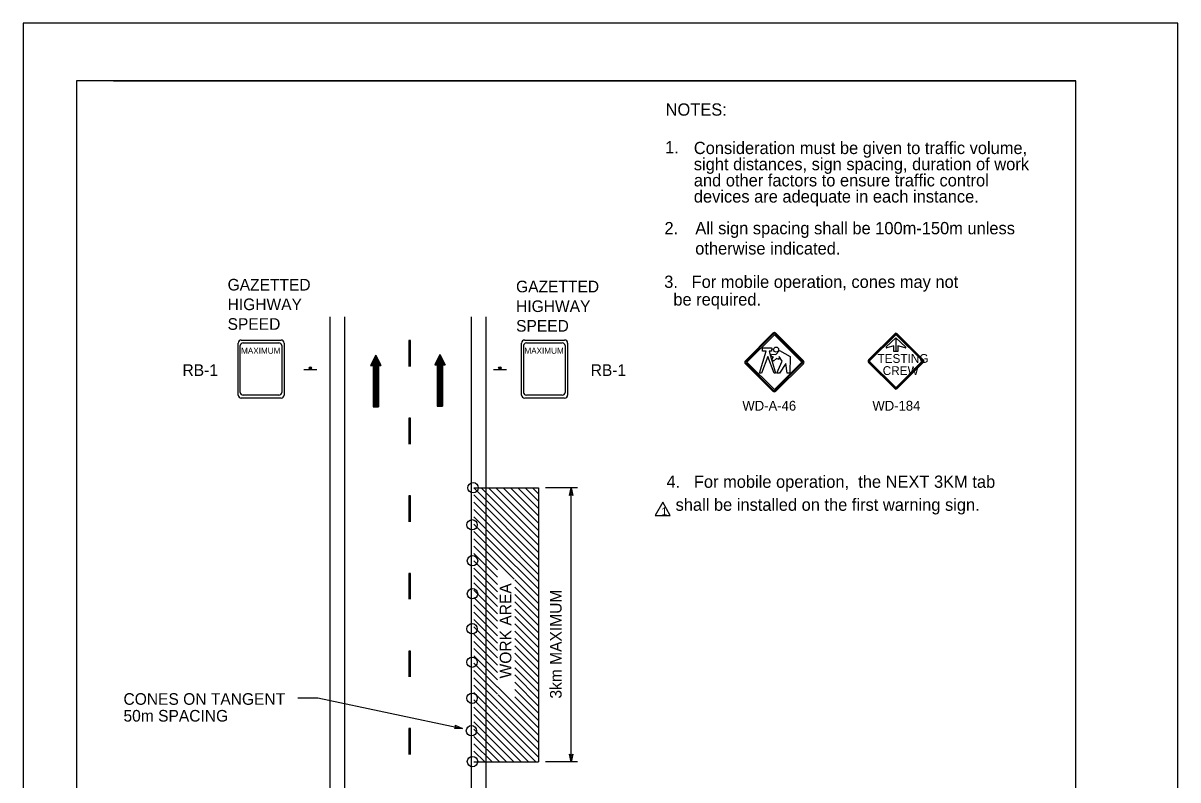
# Model space of a CAD drawing. Extents: x 1333 to 1549, y 120 to 399.
# Drawn here: x 1333.4 to 1549.4, y 257.2 to 398.8 of the extents above; entities that cross this region are included whole.
import ezdxf

# ---------------------------------------------------------------- set-up
doc = ezdxf.new("R2010")
doc.units = 0
for name, color, linetype in [('Level 1', 7, 'Continuous'), ('Level 10', 7, 'Continuous'), ('Level 2', 7, 'Continuous'), ('Level 22', 7, 'Continuous'), ('Level 3', 7, 'Continuous'), ('Level 44', 7, 'Continuous'), ('Level 60', 7, 'Continuous'), ('Level 61', 7, 'Continuous'), ('Level 62', 7, 'Continuous')]:
    doc.layers.add(name, color=color, linetype=linetype)

msp = doc.modelspace()

# ---------------------------------------------------------------- linework, layer by layer
at = {"layer": 'Level 1'}
for p, q in [((1468.47, 335.62), (1473.6, 340.75)), ((1468.62, 335.48), (1473.74, 340.61)), ((1468.76, 335.34), (1473.88, 340.46)), ((1473.85, 341.01), (1473.85, 341.01)), ((1473.89, 341.04), (1473.89, 341.04)), ((1473.89, 340.46), (1479.02, 335.34)), ((1474.03, 340.61), (1479.16, 335.48)), ((1474.18, 340.75), (1479.31, 335.62)), ((1491.5, 335.76), (1496.4, 340.66)), ((1496.49, 340.57), (1491.59, 335.67)), ((1491.59, 335.67), (1496.49, 340.57)), ((1491.68, 335.58), (1496.58, 340.48)), ((1496.62, 339.87), (1496.62, 337.35)), ((1496.67, 340.48), (1501.56, 335.58)), ((1496.85, 340.66), (1501.74, 335.76)), ((1473.6, 329.92), (1468.47, 335.05)), ((1473.74, 330.06), (1468.62, 335.19)), ((1473.88, 330.2), (1468.76, 335.33)), ((1473.85, 335.24), (1473.85, 335.24)), ((1479.02, 335.33), (1473.89, 330.2)), ((1479.16, 335.19), (1474.03, 330.06)), ((1479.31, 335.05), (1474.18, 329.92)), ((1496.4, 330.42), (1491.5, 335.31)), ((1496.58, 330.59), (1491.68, 335.49)), ((1496.64, 330.62), (1501.54, 335.52)), ((1496.64, 330.62), (1501.54, 335.52)), ((1496.64, 330.62), (1501.54, 335.52)), ((1501.54, 335.52), (1496.64, 330.62)), ((1501.56, 335.49), (1496.67, 330.59)), ((1501.74, 335.31), (1496.85, 330.42)), ((1501.97, 335.54), (1501.97, 335.54))]:
    msp.add_line(p, q, dxfattribs=at)
for points in [[(1472.32, 337.42), (1471.69, 337.42), (1471.69, 338.02), (1473.34, 338.02), (1473.34, 337.93), (1473.41, 337.93), (1473.41, 337.69), (1473.34, 337.69), (1473.34, 337.42), (1472.88, 337.42), (1474.09, 333.29), (1473.83, 333.29), (1472.64, 336.41), (1471.45, 333.29), (1471.13, 333.29)], [(1472.32, 337.42), (1471.69, 337.42), (1471.69, 338.02), (1473.34, 338.02), (1473.34, 337.93), (1473.41, 337.93), (1473.41, 337.69), (1473.34, 337.69), (1473.34, 337.42), (1472.88, 337.42), (1474.09, 333.29), (1473.83, 333.29), (1472.64, 336.41), (1471.45, 333.29), (1471.13, 333.29)], [(1473.32, 336.85), (1474.18, 336.77), (1474.87, 337.55), (1476.82, 336.42), (1476.76, 333.29), (1476.29, 333.29), (1476.01, 335.08), (1474.87, 333.29), (1474.35, 333.29), (1475.33, 335.51), (1474.81, 336.41), (1474.71, 335.85), (1474.26, 336.03), (1473.71, 335.51), (1473.37, 335.82), (1473.74, 336.25), (1473.24, 336.48)], [(1473.32, 336.85), (1474.18, 336.77), (1474.87, 337.55), (1476.82, 336.42), (1476.76, 333.29), (1476.29, 333.29), (1476.01, 335.08), (1474.87, 333.29), (1474.35, 333.29), (1475.33, 335.51), (1474.81, 336.41), (1474.71, 335.85), (1474.26, 336.03), (1473.71, 335.51), (1473.37, 335.82), (1473.74, 336.25), (1473.24, 336.48)], [(1452.99, 309.13), (1451.57, 306.66), (1454.4, 306.66)]]:
    msp.add_lwpolyline(points, close=True, dxfattribs=at)
for centre, radius, start, end in [((1473.89, 340.46), 0.409, 45.0349, 135), ((1473.89, 340.46), 0.208, 45.0349, 135), ((1473.89, 340.46), 0.00624, 45.0349, 135), ((1496.62, 340.43), 0.32, 44.9995, 135.0002), ((1496.62, 340.43), 0.194, 44.9995, 135.0002), ((1496.62, 340.43), 0.194, 44.9995, 135.0002), ((1496.62, 340.43), 0.068, 44.9995, 135.0002), ((1496.62, 340.43), 0.026, 45, 135), ((1496.62, 340.43), 0.026, 45, 135), ((1496.62, 340.43), 0.026, 45, 135), ((1468.76, 335.33), 0.409, 135, 224.9651), ((1468.76, 335.33), 0.208, 135, 224.9651), ((1468.76, 335.33), 0.00624, 135, 224.9651), ((1479.02, 335.33), 0.00624, 315, 45.0346), ((1479.02, 335.33), 0.208, 315, 45.0346), ((1479.02, 335.33), 0.409, 315, 45.0346), ((1491.73, 335.54), 0.32, 135.0005, 225), ((1491.73, 335.54), 0.194, 135.0005, 225), ((1491.73, 335.54), 0.194, 135.0005, 225), ((1491.73, 335.54), 0.194, 135.0005, 225), ((1491.73, 335.54), 0.068, 135.0005, 225), ((1501.52, 335.54), 0.026, 315, 45), ((1501.52, 335.54), 0.026, 315, 45), ((1501.52, 335.54), 0.026, 315, 45), ((1501.52, 335.54), 0.068, 315.0005, 44.9999), ((1501.52, 335.54), 0.194, 315.0005, 44.9999), ((1501.52, 335.54), 0.194, 315.0005, 44.9999), ((1501.52, 335.54), 0.32, 315.0005, 44.9999), ((1496.62, 330.64), 0.068, 224.9995, 315), ((1496.62, 330.64), 0.026, 225, 315), ((1496.62, 330.64), 0.026, 225, 315), ((1496.62, 330.64), 0.026, 225, 315), ((1473.89, 330.21), 0.409, 224.965, 315), ((1473.89, 330.21), 0.208, 224.965, 315), ((1473.89, 330.21), 0.00624, 224.965, 315), ((1496.62, 330.64), 0.32, 224.9995, 315)]:
    msp.add_arc(centre, radius, start, end, dxfattribs=at)
at = {"layer": 'Level 10'}
for p, q in [((1390.76, 343.79), (1390.76, 162.28)), ((1393.49, 343.79), (1393.49, 162.28)), ((1417.2, 343.79), (1417.2, 162.28)), ((1419.94, 343.79), (1419.94, 162.28)), ((1399.33, 336.66), (1398.36, 334.72)), ((1398.48, 334.97), (1398.48, 334.72)), ((1398.6, 335.21), (1398.6, 334.72)), ((1398.73, 335.45), (1398.73, 334.72)), ((1398.85, 335.69), (1398.85, 326.98)), ((1398.97, 335.93), (1398.97, 326.98)), ((1399.09, 336.18), (1399.09, 326.98)), ((1399.21, 336.42), (1399.21, 326.98)), ((1399.33, 336.66), (1399.33, 326.98)), ((1399.33, 336.66), (1400.3, 334.72)), ((1399.45, 336.42), (1399.45, 326.98)), ((1399.57, 336.18), (1399.57, 326.98)), ((1399.69, 335.93), (1399.69, 326.98)), ((1399.81, 335.69), (1399.81, 326.98)), ((1399.93, 335.45), (1399.93, 334.72)), ((1400.06, 335.21), (1400.06, 334.72)), ((1400.18, 334.97), (1400.18, 334.72)), ((1411.32, 336.78), (1410.35, 334.85)), ((1410.35, 334.85), (1410.83, 334.85)), ((1410.47, 335.09), (1410.47, 334.85)), ((1410.59, 335.33), (1410.59, 334.85)), ((1410.71, 335.57), (1410.71, 334.85)), ((1410.83, 335.82), (1410.83, 327.11)), ((1410.83, 334.85), (1410.83, 327.11)), ((1410.95, 336.06), (1410.95, 327.11)), ((1411.07, 336.3), (1411.07, 327.11)), ((1411.19, 336.54), (1411.19, 327.11)), ((1411.32, 336.78), (1411.32, 327.11)), ((1411.32, 336.78), (1412.28, 334.85)), ((1411.44, 336.54), (1411.44, 327.11)), ((1411.56, 336.3), (1411.56, 327.11)), ((1411.68, 336.06), (1411.68, 327.11)), ((1411.8, 335.82), (1411.8, 327.11)), ((1411.8, 334.85), (1411.8, 327.11)), ((1411.8, 334.85), (1412.28, 334.85)), ((1411.92, 335.57), (1411.92, 334.85)), ((1412.04, 335.33), (1412.04, 334.85)), ((1412.16, 335.09), (1412.16, 334.85)), ((1398.36, 334.72), (1398.85, 334.72)), ((1398.85, 334.72), (1398.85, 326.98)), ((1399.81, 334.72), (1399.81, 326.98)), ((1399.81, 334.72), (1400.3, 334.72)), ((1398.85, 326.98), (1399.81, 326.98)), ((1410.83, 327.11), (1411.8, 327.11)), ((1417.68, 311.86), (1429.78, 311.86)), ((1417.68, 311.86), (1429.78, 299.77)), ((1417.68, 311.86), (1429.78, 311.86)), ((1419.05, 311.86), (1429.78, 301.14)), ((1420.42, 311.86), (1429.78, 302.51)), ((1421.79, 311.86), (1429.78, 303.88)), ((1423.16, 311.86), (1429.78, 305.24)), ((1424.53, 311.86), (1429.78, 306.61)), ((1425.89, 311.86), (1429.78, 307.98)), ((1427.26, 311.86), (1429.78, 309.35)), ((1428.63, 311.86), (1429.78, 310.72)), ((1429.78, 311.86), (1429.78, 260.58)), ((1437.06, 311.86), (1431.05, 311.86)), ((1435.87, 260.58), (1435.87, 311.86)), ((1417.68, 310.5), (1429.78, 298.4)), ((1417.68, 309.13), (1424.43, 302.38)), ((1417.68, 307.76), (1423.07, 302.38)), ((1417.68, 306.39), (1422.12, 301.95)), ((1417.68, 305.02), (1422.12, 300.58)), ((1417.68, 303.65), (1425.36, 295.98)), ((1417.68, 302.29), (1425.19, 294.78)), ((1417.68, 300.92), (1422.12, 296.48)), ((1421.44, 301.27), (1429.78, 292.93)), ((1422.12, 301.95), (1429.78, 294.3)), ((1423.07, 302.38), (1429.78, 295.66)), ((1424.43, 302.38), (1429.78, 297.03)), ((1417.68, 299.55), (1422.12, 295.11)), ((1417.68, 298.18), (1422.12, 293.74)), ((1417.68, 296.81), (1422.12, 292.38)), ((1425.34, 295.99), (1429.78, 291.56)), ((1417.68, 295.44), (1422.12, 291.01)), ((1417.68, 294.07), (1422.12, 289.64)), ((1425.34, 294.62), (1429.78, 290.19)), ((1417.68, 292.71), (1422.12, 288.27)), ((1425.34, 293.26), (1429.78, 288.82)), ((1425.34, 291.89), (1429.78, 287.45)), ((1417.68, 291.34), (1422.12, 286.9)), ((1417.68, 289.97), (1422.12, 285.53)), ((1425.34, 290.52), (1429.78, 286.09)), ((1417.68, 288.6), (1417.69, 288.59)), ((1417.68, 288.6), (1422.12, 284.16)), ((1425.34, 289.15), (1429.78, 284.72)), ((1425.34, 287.78), (1429.78, 283.35)), ((1417.68, 287.23), (1422.12, 282.8)), ((1417.68, 285.87), (1422.12, 281.43)), ((1425.34, 286.41), (1429.78, 281.98)), ((1417.68, 284.5), (1422.12, 280.06)), ((1417.68, 283.13), (1422.12, 278.69)), ((1425.34, 285.05), (1429.78, 280.61)), ((1425.34, 283.68), (1429.78, 279.24)), ((1417.68, 281.76), (1422.12, 277.32)), ((1425.34, 282.31), (1429.78, 277.88)), ((1425.34, 280.94), (1429.78, 276.51)), ((1417.68, 280.39), (1422.12, 275.95)), ((1417.68, 279.02), (1422.12, 274.59)), ((1425.34, 279.57), (1429.78, 275.14)), ((1417.68, 277.66), (1422.12, 273.22)), ((1425.34, 278.2), (1429.78, 273.77)), ((1425.34, 276.84), (1429.78, 272.4)), ((1417.68, 276.29), (1422.12, 271.85)), ((1417.68, 274.92), (1422.12, 270.48)), ((1422.07, 274.63), (1429.78, 266.93)), ((1425.34, 275.47), (1429.78, 271.03)), ((1384.77, 272.57), (1388.49, 272.57)), ((1388.49, 272.57), (1415.56, 266.86)), ((1417.68, 273.55), (1422.12, 269.11)), ((1417.68, 272.18), (1422.12, 267.74)), ((1422.2, 273.14), (1429.78, 265.56)), ((1425.34, 274.1), (1429.78, 269.67)), ((1425.34, 272.73), (1429.78, 268.3)), ((1417.68, 270.81), (1427.91, 260.58)), ((1422.05, 271.92), (1429.78, 264.19)), ((1422.19, 270.41), (1429.78, 262.82)), ((1417.68, 269.44), (1426.55, 260.58)), ((1417.68, 268.08), (1425.18, 260.58)), ((1422.13, 269.1), (1429.78, 261.45)), ((1417.68, 266.71), (1423.81, 260.58)), ((1422.11, 267.75), (1429.28, 260.58)), ((1417.68, 265.34), (1422.44, 260.58)), ((1417.68, 263.97), (1421.07, 260.58)), ((1417.68, 262.6), (1419.7, 260.58)), ((1417.68, 260.58), (1429.78, 260.58)), ((1437.06, 260.58), (1431.05, 260.58))]:
    msp.add_line(p, q, dxfattribs=at)
for points in [[(1435.87, 311.86), (1436.17, 310.41), (1435.87, 310.65), (1435.57, 310.41)], [(1415.56, 266.86), (1414.08, 266.86), (1414.37, 267.11), (1414.2, 267.45)], [(1435.87, 260.58), (1435.57, 262.03), (1435.87, 261.79), (1436.17, 262.03)]]:
    msp.add_lwpolyline(points, close=True, dxfattribs=at)
for centre in [(1417.52, 311.86), (1417.33, 304.93), (1417.42, 298.2), (1417.42, 292.04), (1417.33, 285.49), (1417.33, 279.23), (1417.33, 272.49), (1417.23, 266.42), (1417.42, 260.64)]:
    msp.add_circle(centre, 0.968, dxfattribs=at)
at = {"layer": 'Level 2'}
for p, q in [((1405.51, 339.37), (1405.51, 334.53)), ((1405.8, 339.37), (1405.51, 339.37)), ((1405.8, 334.53), (1405.8, 339.37)), ((1405.51, 324.85), (1405.51, 320.01)), ((1405.8, 324.85), (1405.51, 324.85)), ((1405.8, 320.01), (1405.8, 324.85)), ((1405.51, 310.34), (1405.51, 305.5)), ((1405.8, 310.34), (1405.51, 310.34)), ((1405.8, 305.5), (1405.8, 310.34)), ((1405.51, 295.82), (1405.51, 290.99)), ((1405.8, 295.82), (1405.51, 295.82)), ((1405.8, 290.99), (1405.8, 295.82)), ((1405.51, 281.31), (1405.51, 276.47)), ((1405.8, 281.31), (1405.51, 281.31)), ((1405.8, 276.47), (1405.8, 281.31)), ((1405.51, 266.8), (1405.51, 261.96)), ((1405.8, 266.8), (1405.51, 266.8)), ((1405.8, 261.96), (1405.8, 266.8))]:
    msp.add_line(p, q, dxfattribs=at)
for centre, radius, start, end in [((1496.62, 340.43), 0.32, 44.9995, 135.0002), ((1496.62, 340.43), 0.194, 44.9995, 135.0002), ((1491.73, 335.54), 0.32, 135.0005, 225), ((1501.52, 335.54), 0.194, 315.0005, 44.9999), ((1501.52, 335.54), 0.32, 315.0005, 44.9999), ((1496.62, 330.64), 0.194, 224.9995, 315)]:
    msp.add_arc(centre, radius, start, end, dxfattribs=at)
at = {"layer": 'Level 22'}
msp.add_line((1350.24, 387.94), (1530.24, 387.94), dxfattribs=at)
at = {"layer": 'Level 3'}
for centre, start, end in [((1496.62, 340.43), 45, 135), ((1496.62, 340.43), 45, 135), ((1501.52, 335.54), 315, 45), ((1501.52, 335.54), 315, 45), ((1496.62, 330.64), 225, 315), ((1496.62, 330.64), 225, 315)]:
    msp.add_arc(centre, 0.026, start, end, dxfattribs=at)
at = {"layer": 'Level 44'}
for p, q in [((1374.18, 339.48), (1381.63, 339.48)), ((1427.18, 339.48), (1434.63, 339.48)), ((1373.61, 329.2), (1373.61, 338.91)), ((1373.99, 329.69), (1373.99, 338.43)), ((1374.51, 338.95), (1381.21, 338.95)), ((1381.73, 338.43), (1381.73, 329.69)), ((1382.2, 338.91), (1382.2, 329.2)), ((1426.6, 329.2), (1426.6, 338.91)), ((1426.99, 329.69), (1426.99, 338.43)), ((1427.5, 338.95), (1434.21, 338.95)), ((1434.73, 338.43), (1434.73, 329.69)), ((1435.2, 338.91), (1435.2, 329.2)), ((1385.88, 333.98), (1388.29, 333.98)), ((1421.34, 333.98), (1423.76, 333.98)), ((1373.61, 329.2), (1373.61, 329.2)), ((1373.99, 329.69), (1373.99, 329.69)), ((1381.63, 328.62), (1374.18, 328.62)), ((1381.21, 329.17), (1374.51, 329.17)), ((1426.6, 329.2), (1426.6, 329.2)), ((1426.99, 329.69), (1426.99, 329.69)), ((1434.63, 328.62), (1427.18, 328.62)), ((1434.21, 329.17), (1427.5, 329.17))]:
    msp.add_line(p, q, dxfattribs=at)
for centre, radius in [((1474.21, 337.69), 0.471), ((1474.21, 337.69), 0.471), ((1387.09, 334.25), 0.242), ((1387.09, 334.25), 0.121), ((1422.55, 334.25), 0.242), ((1422.55, 334.25), 0.121)]:
    msp.add_circle(centre, radius, dxfattribs=at)
for centre, radius, start, end in [((1374.18, 338.91), 0.575, 90, 180), ((1381.63, 338.91), 0.575, 360, 90), ((1427.18, 338.91), 0.575, 90, 180), ((1434.63, 338.91), 0.575, 360, 90), ((1374.51, 338.43), 0.517, 90, 180), ((1381.21, 338.43), 0.517, 360, 90), ((1427.5, 338.43), 0.517, 90, 180), ((1434.21, 338.43), 0.517, 360, 90), ((1374.18, 329.2), 0.575, 180, 270), ((1374.51, 329.69), 0.517, 180, 270), ((1381.21, 329.69), 0.517, 270, 360), ((1381.63, 329.2), 0.575, 270, 360), ((1427.18, 329.2), 0.575, 180, 270), ((1427.5, 329.69), 0.517, 180, 270), ((1434.21, 329.69), 0.517, 270, 360), ((1434.63, 329.2), 0.575, 270, 360)]:
    msp.add_arc(centre, radius, start, end, dxfattribs=at)
at = {"layer": 'Level 60'}
for p, q in [((1549.36, 398.75), (1549.36, 398.75)), ((1494.92, 338.04), (1494.92, 338.04))]:
    msp.add_line(p, q, dxfattribs=at)
for points in [[(1549.36, 398.75), (1333.36, 398.75), (1333.36, 119.75), (1549.36, 119.75)], [(1530.24, 387.94), (1343.36, 387.94), (1343.36, 130.56), (1530.24, 130.56)]]:
    msp.add_lwpolyline(points, close=True, dxfattribs=at)
for points in [[(1494.82, 338.23), (1496.62, 339.87), (1498.42, 338.23)], [(1498.32, 338.04), (1496.99, 338.38), (1496.99, 337.35), (1496.25, 337.35), (1496.25, 338.38), (1494.92, 338.04)]]:
    msp.add_lwpolyline(points, dxfattribs=at)
for centre, start, end in [((1494.9, 338.15), 132.3048, 284.4075), ((1498.35, 338.15), 255.5925, 47.6952)]:
    msp.add_arc(centre, 0.113, start, end, dxfattribs=at)
at = {"layer": 'Level 61'}
msp.add_line((1494.92, 338.04), (1494.92, 338.04), dxfattribs=at)
for points in [[(1494.82, 338.23), (1496.62, 339.87), (1498.42, 338.23)], [(1498.32, 338.04), (1496.99, 338.38), (1496.99, 337.35), (1496.25, 337.35), (1496.25, 338.38), (1494.92, 338.04)]]:
    msp.add_lwpolyline(points, dxfattribs=at)
for centre, start, end in [((1494.9, 338.15), 132.3048, 284.4075), ((1498.35, 338.15), 255.5925, 47.6952)]:
    msp.add_arc(centre, 0.113, start, end, dxfattribs=at)
at = {"layer": 'Level 62'}
for p, q in [((1491.59, 335.67), (1496.49, 340.57)), ((1496.76, 340.57), (1501.65, 335.67)), ((1494.92, 338.04), (1494.92, 338.04)), ((1496.49, 330.5), (1491.59, 335.4)), ((1501.65, 335.4), (1496.76, 330.5))]:
    msp.add_line(p, q, dxfattribs=at)
for points in [[(1494.82, 338.23), (1496.62, 339.87), (1498.42, 338.23)], [(1498.32, 338.04), (1496.99, 338.38), (1496.99, 337.35), (1496.25, 337.35), (1496.25, 338.38), (1494.92, 338.04)]]:
    msp.add_lwpolyline(points, dxfattribs=at)
for centre, radius, start, end in [((1496.62, 340.43), 0.194, 44.9995, 135.0002), ((1494.9, 338.15), 0.113, 132.3048, 284.4075), ((1498.35, 338.15), 0.113, 255.5925, 47.6952), ((1491.73, 335.54), 0.194, 135.0005, 225), ((1501.52, 335.54), 0.194, 315.0005, 44.9999), ((1496.62, 330.64), 0.194, 224.9995, 315)]:
    msp.add_arc(centre, radius, start, end, dxfattribs=at)

# ---------------------------------------------------------------- texts
at = {"layer": 'Level 1'}
msp.add_text('1', height=1.45, rotation=360, dxfattribs=at).set_placement((1452.76, 306.72))
at = {"layer": 'Level 10'}
for s, height, p in [('NOTES:', 2.298, (1453.54, 381.44)), ('1.', 2.298, (1453.44, 374.38)), ('Consideration must be given to traffic volume,', 2.298, (1458.82, 374.26)), ('sight distances, sign spacing, duration of work', 2.298, (1458.82, 371.24)), ('and other factors to ensure traffic control ', 2.298, (1458.82, 368.21)), ('devices are adequate in each instance.', 2.298, (1458.82, 365.19)), ('2.', 2.298, (1453.33, 359.26)), ('All sign spacing shall be 100m-150m unless', 2.298, (1459.1, 359.26)), ('otherwise indicated.', 2.298, (1459.08, 355.47)), ('GAZETTED', 2.177, (1371.61, 348.74)), ('GAZETTED', 2.177, (1425.57, 348.4)), ('3.   For mobile operation, cones may not', 2.298, (1453.28, 349.23)), ('  be required.', 2.298, (1453.28, 345.93)), ('HIGHWAY', 2.177, (1371.61, 345.07)), ('HIGHWAY', 2.177, (1425.57, 344.72)), ('SPEED', 2.177, (1371.61, 341.39)), ('SPEED', 2.177, (1425.57, 341.05)), ('WD-A-46', 1.829, (1467.9, 326.28)), ('WD-184', 1.829, (1492.22, 326.28)), ('4.   For mobile operation,  the NEXT 3KM tab ', 2.298, (1453.7, 311.84)), ('  shall be installed on the first warning sign.', 2.298, (1453.7, 307.54))]:
    msp.add_text(s, height=height, dxfattribs=at).set_placement(p)
for s, height, rotation, p in [('RB-1', 2.177, 360, (1363.18, 332.77)), ('RB-1', 2.177, 360, (1439.53, 332.77)), ('WORK AREA', 2.178, 90, (1424.69, 276.19)), ('3km MAXIMUM', 2.1776, 90, (1434.09, 272.42))]:
    msp.add_text(s, height=height, rotation=rotation, dxfattribs=at).set_placement(p)
at = {"layer": 'Level 44'}
for p in [(1374.13, 336.9), (1427.13, 336.9)]:
    msp.add_text('MAXIMUM', height=1.139, rotation=360, dxfattribs=at).set_placement(p)
for s, p in [('CONES ON TANGENT', (1352.14, 271.26)), ('50m SPACING', (1352.14, 268.12))]:
    msp.add_text(s, height=2.1771, dxfattribs=at).set_placement(p)
at = {"layer": 'Level 62'}
for s, p in [('TESTING', (1493.17, 335.21)), ('CREW', (1494.15, 332.94))]:
    msp.add_text(s, height=1.646, rotation=360, dxfattribs=at).set_placement(p)

doc.saveas('drawing.dxf')
